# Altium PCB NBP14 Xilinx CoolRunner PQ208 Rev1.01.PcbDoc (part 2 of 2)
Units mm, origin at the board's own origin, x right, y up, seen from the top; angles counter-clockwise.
Board outline 69 x 80.99 mm, 2 copper layers (Top Layer, Bottom Layer); 33 components, 179 nets, 478 pads, 87 vias.
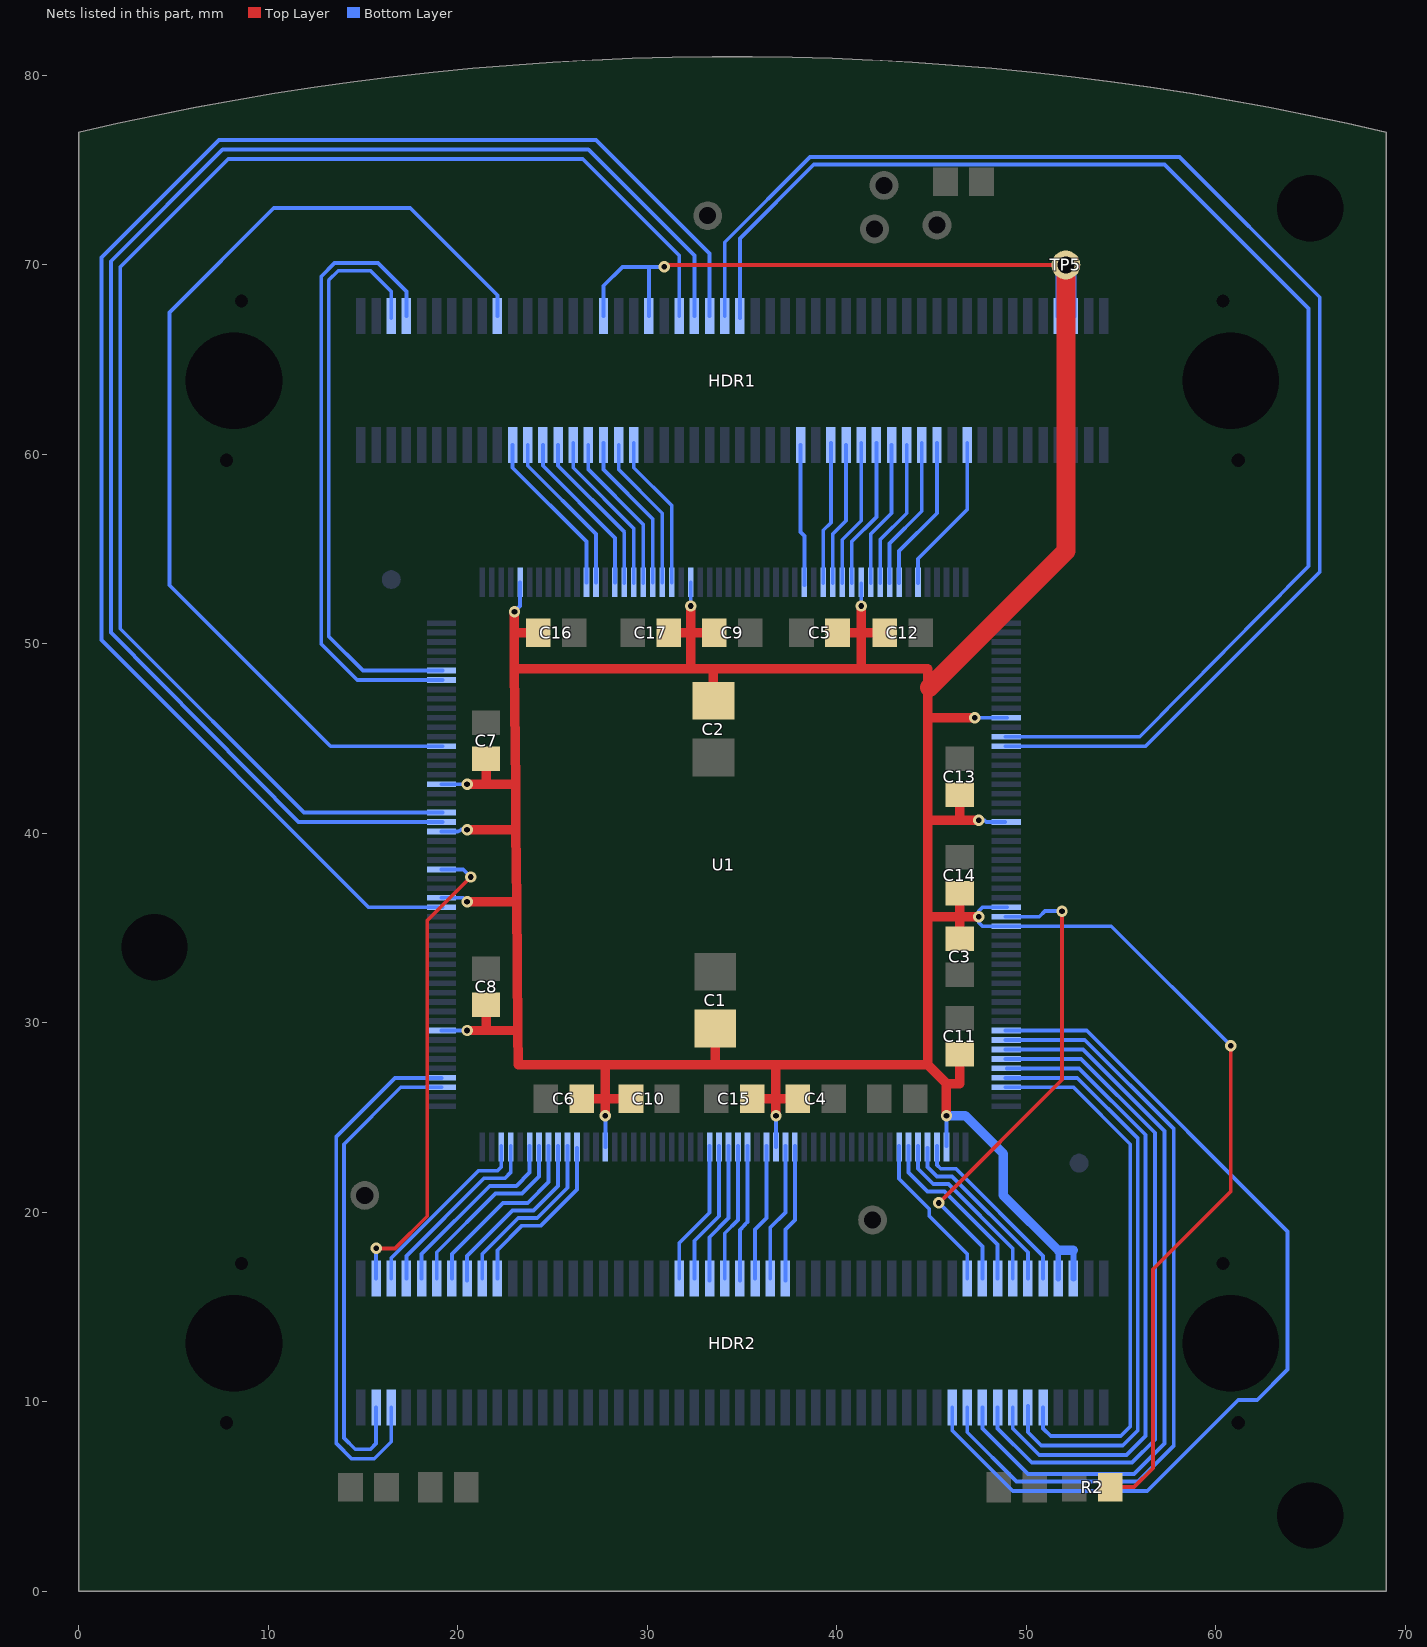
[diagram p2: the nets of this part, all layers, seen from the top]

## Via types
v1: diameter 0.6, hole 0.3, Top Layer to Bottom Layer, tented both sides, 85 vias
v2: diameter 0.9, hole 0.5, Top Layer to Bottom Layer, tented both sides, 2 vias

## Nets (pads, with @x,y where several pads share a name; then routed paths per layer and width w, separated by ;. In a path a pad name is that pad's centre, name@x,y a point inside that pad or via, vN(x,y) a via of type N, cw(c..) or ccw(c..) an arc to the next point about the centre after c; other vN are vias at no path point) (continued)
RAM_ADDR0: HDR1.21 U1.12 | length 8.9
  Bottom Layer w0.2: HDR1.21@22.9,60.5 22.9,59.3 26.8,55.4 U1.12@26.8,53.25
RAM_ADDR1: HDR1.25 U1.15 | length 8.8
  Bottom Layer w0.2: HDR1.25@24.5,60.5 24.5,59.4 28.3,55.6 U1.15@28.3,53.25
RAM_ADDR2: HDR1.29 U1.17 | length 8.7
  Bottom Layer w0.2: HDR1.29@26.1,60.6 HDR1.29@26.1,60.5 26.1,59.3 29.3,56.1 U1.17@29.3,53.2
RAM_ADDR3: HDR1.33 U1.19 | length 8.4
  Bottom Layer w0.2: HDR1.33@27.7,60.6 27.7,59.2 30.3,56.6 U1.19@30.3,53.25
RAM_ADDR4: HDR1.65 U1.38 | length 7.6
  Bottom Layer w0.2: U1.38@39.8,53.2 39.8,55.8 40.5,56.5 HDR1.65@40.5,60.5
RAM_ADDR5: HDR1.69 U1.40 | length 7.9
  Bottom Layer w0.2: U1.40@40.8,53.2 40.8,55.4 42.1,56.7 HDR1.69@42.1,60.6
RAM_ADDR6: HDR1.73 U1.43 | length 7.9
  Bottom Layer w0.2: U1.43@42.3,53.2 42.3,55.5 43.7,56.9 HDR1.73@43.7,60.5
RAM_ADDR7: HDR1.77 U1.45 | length 8.2
  Bottom Layer w0.2: U1.45@43.3,53.2 43.3,54.9 45.3,56.9 HDR1.77@45.3,60.5 HDR1.77@45.3,60.6
RAM_ADDR8: HDR1.75 U1.44 | length 8.1
  Bottom Layer w0.2: U1.44@42.8,53.2 42.8,55.3 44.5,57 HDR1.75@44.5,60.6
RAM_ADDR9: HDR1.71 U1.42 | length 7.8
  Bottom Layer w0.2: U1.42@41.8,53.2 41.8,55.8 42.9,56.9 HDR1.71@42.9,60.5
RAM_ADDR10: HDR1.67 U1.39 | length 7.8
  Bottom Layer w0.2: U1.39@40.3,53.2 40.3,55.5 41.3,56.5 HDR1.67@41.3,60.6
RAM_ADDR11: HDR1.63 U1.37 | length 7.6
  Bottom Layer w0.2: U1.37@39.3,53.2 39.3,56 39.7,56.4 HDR1.63@39.7,60.6
RAM_ADDR12: HDR1.59 U1.35 | length 7.5
  Bottom Layer w0.2: HDR1.59@38.1,60.5 38.1,55.9 38.3,55.7 U1.35@38.3,53.1
RAM_ADDR13: HDR1.35 U1.20 | length 8.2
  Bottom Layer w0.2: HDR1.35@28.5,60.5 28.5,59.2 30.8,56.9 U1.20@30.8,53.25
RAM_ADDR14: HDR1.31 U1.18 | length 8.5
  Bottom Layer w0.2: HDR1.31@26.9,60.5 26.9,59.2 29.8,56.3 U1.18@29.8,53.2
RAM_ADDR15: HDR1.27 U1.16 | length 8.7
  Bottom Layer w0.2: HDR1.27@25.3,60.5 25.3,59.4 28.8,55.9 U1.16@28.8,53.2
RAM_ADDR16: HDR1.23 U1.13 | length 8.7
  Bottom Layer w0.2: HDR1.23@23.7,60.5 23.7,59.4 27.3,55.8 U1.13@27.3,53.25
RAM_CS: HDR1.37 U1.21 | length 8.2
  Bottom Layer w0.2: HDR1.37@29.3,60.6 29.3,59.3 31.3,57.3 U1.21@31.3,53.25
RED0: HDR1.6 U1.203 | length 30.9
  Bottom Layer w0.2: HDR1.6@16.5,67.2 16.5,68.6 15.4,69.7 13.7,69.7 13.2,69.2 13.2,50.4 15,48.6 U1.203@19.2,48.6
RED1: HDR1.8 U1.202 | length 33.3
  Bottom Layer w0.2: HDR1.8@17.3,67.3 17.3,68.6 15.8,70.1 13.5,70.1 12.8,69.4 12.8,50 14.7,48.1 U1.202@19.2,48.1
REF_CLK: HDR2.4 U1.182 | length 25.7
  Top Layer w0.2: v1(15.7,18.1) 16.7,18.1 18.4,19.8 18.4,35.4 v1@20.8,37.8
  Bottom Layer w0.2: HDR2.4@15.7,16.5 v1(15.7,18.1) ; U1.182@19.15,38.1 20.3,38.1 v1(20.7,37.7)
SCL: HDR2.5 U1.160 | length 28.4
  Bottom Layer w0.2: HDR2.5@16.5,9.7 16.5,7.9 15.6,7 14.4,7 13.6,7.8 13.6,24 16.7,27.1 U1.160@19.15,27.1
SDA: HDR2.3 U1.159 | length 25.9
  Bottom Layer w0.2: HDR2.3@15.7,9.7 15.7,7.8 15.4,7.5 14.6,7.5 14,8.1 14,23.6 17,26.6 U1.159@19.15,26.6
SP0: HDR2.79 U1.96 | length 49.5
  Bottom Layer w0.2: HDR2.79@46.1,9.7 46.1,8.5 49.3,5.3 56.4,5.3 61.2,10.1 62.2,10.1 63.8,11.7 63.8,19 53.2,29.6 U1.96@48.9,29.6
SP1: HDR2.81 U1.97 | length 41.6
  Bottom Layer w0.2: HDR2.81@46.9,9.7 46.9,8.4 49.5,5.8 55.9,5.8 57.8,7.7 57.8,24.4 53.1,29.1 U1.97@48.9,29.1
SP2: HDR2.83 U1.98 | length 39
  Bottom Layer w0.2: HDR2.83@47.7,9.7 47.7,8.6 50.1,6.2 55.7,6.2 57.3,7.8 57.3,24.3 53,28.6 U1.98@48.9,28.6
SP3: HDR2.85 U1.99 | length 36.4
  Bottom Layer w0.2: HDR2.85@48.5,9.7 48.5,8.6 50.3,6.8 55.6,6.8 56.8,8 56.8,24.2 52.9,28.1 U1.99@48.9,28.1
SP4: HDR2.87 U1.100 | length 33.7
  Bottom Layer w0.2: U1.100@49,27.6 52.8,27.6 56.3,24.1 56.3,8.2 55.3,7.2 50.7,7.2 49.3,8.6 HDR2.87@49.3,9.7
SP5: HDR2.89 U1.101 | length 31.5
  Bottom Layer w0.2: U1.101@48.9,27.1 52.7,27.1 55.9,23.9 55.9,8.5 55.1,7.7 50.8,7.7 50.1,8.4 HDR2.89@50.1,9.8
SP6: HDR2.91 U1.102 | length 28.8
  Bottom Layer w0.2: U1.102@48.9,26.6 52.5,26.6 55.5,23.6 55.5,8.7 55,8.2 51.3,8.2 50.9,8.6 HDR2.91@50.9,9.7
SP7: HDR2.92 U1.108 | length 9.8
  Bottom Layer w0.2: U1.108@45.3,23.5 45.3,22.5 45.5,22.3 46.3,22.3 50.9,17.7 HDR2.92@50.9,16.5
SP8: HDR2.90 U1.109 | length 9.6
  Bottom Layer w0.2: U1.109@44.8,23.4 44.8,22.4 45.3,21.9 46.1,21.9 50.1,17.9 HDR2.90@50.1,16.5
SP9: HDR2.88 U1.110 | length 9.5
  Bottom Layer w0.2: U1.110@44.3,23.5 44.3,22.3 45.1,21.5 45.9,21.5 49.3,18.1 HDR2.88@49.3,16.5
SP10: HDR2.86 U1.111 | length 9.5
  Bottom Layer w0.2: U1.111@43.8,23.5 43.8,22.1 44.8,21.1 45.7,21.1 48.5,18.3 HDR2.86@48.5,16.5
SP11: HDR2.84 U1.84 | length 26.2
  Top Layer w0.2: v1(45.4,20.5) 51.9,27 v1(51.9,35.9)
  Bottom Layer w0.2: v1(45.4,20.5) 47.7,18.2 HDR2.84@47.7,16.5 ; U1.84@48.9,35.6 50.7,35.6 51,35.9 v1(51.9,35.9)
SP12: HDR2.82 U1.112 | length 8.5
  Bottom Layer w0.2: U1.112@43.3,23.5 43.3,21.774 44.89,20.184 44.89,19.81 46.9,17.8 HDR2.82@46.9,16.5
SPI_CLK: HDR1.46 U1.187 | length 80
  Bottom Layer w0.2: U1.187@19.2,40.6 11.6,40.6 1.7,50.6 1.7,70.2 7.6,76.1 26.9,76.1 32.5,70.5 HDR1.46@32.5,67.3
SPI_DIN: HDR1.44 U1.188 | length 77.3
  Bottom Layer w0.2: U1.188@19.2,41.1 11.9,41.1 2.2,50.8 2.2,69.9 7.9,75.6 26.6,75.6 31.7,70.5 HDR1.44@31.7,67.3
SPI_DOUT: HDR1.50 U1.66 | length 75.1
  Bottom Layer w0.2: HDR1.50@34.1,67.3 34.1,71.2 38.6,75.7 58.1,75.7 65.5,68.3 65.5,53.8 56.3,44.6 U1.66@48.9,44.6
SPI_MODE: HDR1.52 U1.65 | length 72.3
  Bottom Layer w0.2: HDR1.52@34.9,67.2 34.9,71.4 38.8,75.3 57.3,75.3 64.9,67.7 64.9,54.1 56,45.1 U1.65@48.9,45.1
SPI_SEL: HDR1.48 U1.178 | length 84.5
  Bottom Layer w0.2: U1.178@19.2,36.1 15.3,36.1 1.2,50.2 1.2,70.4 7.4,76.6 27.3,76.6 33.3,70.6 HDR1.48@33.3,67.3
SW0: HDR2.44 U1.132 | length 7.7
  Bottom Layer w0.2: HDR2.44@31.7,16.5 31.7,18.385 33.307,19.993 ; 33.3,20 U1.132@33.3,23.5
SW1: HDR2.46 U1.131 | length 7.5
  Bottom Layer w0.2: HDR2.46@32.5,16.5 32.5,18.5 33.8,19.8 U1.131@33.8,23.5
SW2: HDR2.48 U1.130 | length 7.5
  Bottom Layer w0.2: HDR2.48@33.3,16.4 33.3,18.691 34.3,19.7 U1.130@34.3,23.5
SW3: HDR2.50 U1.129 | length 7.3
  Bottom Layer w0.2: HDR2.50@34.1,16.5 34.1,18.9 34.8,19.6 U1.129@34.8,23.5
SW4: HDR2.52 U1.128 | length 7.3
  Bottom Layer w0.2: HDR2.52@34.9,16.4 34.9,19.077 35.3,19.5 U1.128@35.3,23.5
SW5: HDR2.54 U1.126 | length 7.2
  Bottom Layer w0.2: HDR2.54@35.7,16.5 35.7,19.1 36.3,19.7 U1.126@36.3,23.5
SW6: HDR2.56 U1.124 | length 7.3
  Bottom Layer w0.2: HDR2.56@36.5,16.5 36.5,19.2 37.3,20 U1.124@37.3,23.5
SW7: HDR2.58 U1.123 | length 7.3
  Bottom Layer w0.2: HDR2.58@37.3,16.4 37.3,19.1 37.8,19.6 U1.123@37.8,23.5
SWC0: HDR2.18 U1.147 | length 9.4
  Bottom Layer w0.2: HDR2.18@21.3,16.5 21.3,17.8 23.2,19.7 24.2,19.7 25.8,21.3 U1.147@25.8,23.5
SWC1: HDR2.16 U1.148 | length 9.7
  Bottom Layer w0.2: HDR2.16@20.5,16.4 20.5,17.7 22.9,20.1 24,20.1 25.3,21.4 U1.148@25.3,23.5
SWC2: HDR2.14 U1.149 | length 9.9
  Bottom Layer w0.2: HDR2.14@19.7,16.5 19.7,17.8 22.4,20.5 23.7,20.5 24.8,21.6 U1.149@24.8,23.5
SWC3: HDR2.6 U1.154 | length 10
  Bottom Layer w0.2: HDR2.6@16.5,16.5 16.5,17.6 21.1,22.2 22.1,22.2 22.3,22.4 U1.154@22.3,23.5
SWR0: HDR2.20 U1.146 | length 9.2
  Bottom Layer w0.2: HDR2.20@22.1,16.5 22.1,18 23.4,19.3 24.4,19.3 26.3,21.2 U1.146@26.3,23.4
SWR1: HDR2.12 U1.150 | length 10.1
  Bottom Layer w0.2: HDR2.12@18.9,16.5 18.9,17.9 22,21 23.4,21 24.3,21.9 U1.150@24.3,23.5
SWR2: HDR2.10 U1.151 | length 10.2
  Bottom Layer w0.2: HDR2.10@18.1,16.5 18.1,17.8 21.7,21.4 23.1,21.4 23.8,22.1 U1.151@23.8,23.5
SWR3: HDR2.8 U1.153 | length 9.9
  Bottom Layer w0.2: HDR2.8@17.3,16.5 17.3,17.7 21.4,21.8 22.5,21.8 22.8,22.1 U1.153@22.8,23.5
TEST: HDR1.81 U1.47 | length 8.5
  Bottom Layer w0.2: U1.47@44.3,53.2 44.3,54.5 46.9,57.1 HDR1.81@46.9,60.5 HDR1.81@46.9,60.6
VCC: C1.1 C2.1 C3.1 C4.1 C5.1 C6.1 C7.1 C8.1 C9.1 C10.1 C11.1 C12.1 C13.1 C14.1 C15.1 C16.1 C17.1 HDR1.34 HDR1.40 HDR1.94 HDR1.96 HDR2.94 HDR2.96 R2.1 TP5.1 U1.5 U1.23 U1.41 U1.63 U1.74 U1.83 U1.85 U1.107 U1.125 U1.143 U1.165 U1.179 U1.186 U1.191 | length 281.7
  Top Layer w0.2: v1(30.9,69.9) 31,70 31.3,70 TP5.1@52.2,70 ; R2.1@54.4,5.5 55.7,5.5 56.7,6.5 56.7,17 60.8,21.1 v1(60.8,28.8)
  Top Layer w0.5: v1(20.5,29.6) 23.182,29.6 ; v1(20.5,36.4) 23.117,36.4 ; v1(20.5,40.2) 23.081,40.2 ; v1(20.5,42.6) 23.058,42.6 ; 21.5,29.6 C8.1@21.5,30.9 ; 21.5,42.6 C7.1@21.5,44 ; 23,50.6 C16.1@24.3,50.6 ; v1(23,51.7) 23,48.7 ; C6.1@26.5,26 27.8,26 C10.1@29.2,26 ; v1(27.8,25.1) 27.8,27.7 ; C17.1@31.1,50.6 C9.1@33.6,50.6 ; 32.3,48.7 32.3,50.6 v1(32.3,52) ; C2.1@33.5,46.9 33.5,48.7 ; 33.6,27.8 C1.1@33.6,29.7 ; C15.1@35.5,26 C4.1@38,26 ; v1(36.8,25.1) 36.8,27.8 ; C5.1@40.1,50.6 C12.1@42.6,50.6 ; 41.3,48.7 v1(41.3,52) ; 44.8,35.6 v1(47.5,35.6) ; 44.8,40.7 v1(47.5,40.7) ; 44.8,46.1 v1(47.3,46.1) ; v1(45.8,25.1) 45.8,26.8 ; C11.1@46.5,28.3 46.5,26.8 45.8,26.8 ; C3.1@46.5,34.4 C14.1@46.5,36.8 ; 46.5,40.7 C13.1@46.5,42 ; 23,48.7 44.8,48.7 44.8,27.8 ; 23,48.7 23.058,42.6 ; 23.058,42.6 23.081,40.2 ; 23.081,40.2 23.117,36.4 ; 23.117,36.4 23.182,29.6 ; 23.182,29.6 23.2,27.8 44.8,27.8 ; 44.8,27.8 45.8,26.8
  Top Layer w1: 44.9,47.7 52.1,54.9 TP5.1@52.1,70
  Bottom Layer w0.2: U1.165@19.15,29.6 v1(20.5,29.6) ; U1.179@19.15,36.6 20.3,36.6 v1(20.5,36.4) ; U1.186@19.15,40.1 20,40.1 20.2,40.2 v1(20.5,40.2) ; U1.191@19.15,42.6 v1(20.5,42.6) ; v1(23,51.7) 23.3,52 U1.5@23.3,53.25 ; HDR1.34@27.7,67.3 27.7,68.9 28.7,69.9 30.1,69.9 ; U1.143@27.8,23.45 v1(27.8,25.1) ; HDR1.40@30.1,67.3 30.1,67.6 30.1,69.9 ; v1(30.9,69.9) 30.1,69.9 ; v1(32.3,52) U1.23@32.3,53.25 ; U1.125@36.8,23.45 v1(36.8,25.1) ; v1(41.3,52) U1.41@41.3,53.2 ; U1.107@45.8,23.5 v1(45.8,25.1) ; v1(47.3,46.1) U1.63@49,46.1 ; v1(47.5,40.7) 47.8,40.7 47.9,40.6 U1.74@48.9,40.6 ; U1.83@49,36.1 47.7,36.1 47.5,35.9 47.5,35.3 47.7,35.1 54.5,35.1 v1(60.8,28.8)
  Bottom Layer w0.3: HDR2.94@51.7,16.5 51.7,18 ; HDR1.94@51.7,67.3 TP5.1@51.7,70 ; HDR2.96@52.5,16.5 52.5,18 ; HDR1.96@52.5,67.3 TP5.1@52.5,70
  Bottom Layer w0.5: v1(45.8,25.1) 46.8,25.1 48.8,23.1 48.8,20.9 51.7,18 52.5,18
VDRIVE: HDR1.20 U1.195 | length 54.9
  Bottom Layer w0.2: U1.195@19.2,44.6 13.3,44.6 4.8,53.1 4.8,67.5 10.3,73 17.5,73 22.1,68.4 HDR1.20@22.1,67.3
pads on no net: HDR1.91 HDR1.93 HDR1.95 HDR1.97 HDR1.99 HDR1.MH1 HDR1.MH2 HDR1.MH3 HDR1.MH4 HDR1.MH5 HDR1.MH6 HDR2.76 HDR2.78 HDR2.80 HDR2.93 HDR2.95 HDR2.97 HDR2.99 HDR2.MH1 HDR2.MH2 HDR2.MH3 HDR2.MH4 HDR2.MH5 HDR2.MH6 U1.1 U1.2 U1.51 U1.52 U1.53 U1.54 U1.103 U1.104 U1.105 U1.106 U1.155 U1.156 U1.157 U1.158 U1.207 U1.208

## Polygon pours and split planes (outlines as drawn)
VCC on Top Layer "Top Layer-VCC" (solid, remove dead copper, pour order 1001): 21.6,50.3 46.5,50.3 46.5,26.1 21.6,26.1
GND on Top Layer "Top Layer-GND" (solid, remove dead copper, pour order 1000): 0,0 69,0 69,81 0,81
GND on Bottom Layer "Bottom Layer-GND" (solid, remove dead copper, pour order 1002): 0,0 69,0 69,81 0,81

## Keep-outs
Bottom Layer:
  circle w0.2: c16.5,53.4 r2
  circle w0.2: c52.8,22.6 r2
Keep-Out Layer:
  lines w1.8: 68.999,77 ccw(c34.5,-69.801) 0.001,77 0,0 69,0 ; 69.1,0 69.1,77

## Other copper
Bottom Layer:
  rectangle net VCC: 51.6,68.6 52.6,70.6

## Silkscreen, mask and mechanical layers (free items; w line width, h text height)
Top Overlay:
  circle w0.127: c65,73 r2.5
  circle w0.127: c65,4 r2.5
  circle w0.127: c4,34 r2.5
  lines w0.127: 0,1.5 1.5,1.5 1.5,0 ; 0,22.3 1.5,22.3 1.5,23.4 0,23.4 ; 0.001,53.6 1.501,53.6 1.501,54.7 0.001,54.7 ; 0,75.5 1.5,75.5 1.5,77.3 ; 15.7,79.8 15.7,78.1 17,78.1 17,79.9 ; 49.7,80.2 49.7,78.7 51,78.7 51,80.1 ; 67.5,0 67.5,1.5 69,1.5 ; 67.5,77.3 67.5,75.5 69,75.5 ; 68.999,22.3 67.5,22.3 67.5,23.4 69,23.4 ; 69,53.6 67.501,53.6 67.501,54.7 69.001,54.7
  text "PROGRAM" at 16.9,3.1 h0.8
  text "POWER" at 47.6,3.1 h0.8
Bottom Overlay:
  drawing of 852 lines, arcs and shapes, not listed
  text "REV 1.01" at 47.7,76.5 h1.3
  text "NBP14" at 54.9,76.5 h1.3
PCB Boundary:
  the board outline again, w0.25
  text "PCB boundary coincides with centre-line of tracks and arc" at 0,-12 h0.75
Gerber ID:
  text ".Layer_Name" at 0,-6 h0.75
Printout ID:
  text ".Printout_Name" at 0,-10 h0.75
Design Information:
  drawing of 719 lines, arcs and shapes, not listed
  text "NBP14 REV 1.01" at 317.627,202.041 h1.27
  text "DESIGN INFORMATION" at 261.62,201.914 h1.52
  text "BOARD NAME:" at 299.212,201.914 h1.52
  text "BOARD TECHNOLOGY" at 261.62,199.374 h1.52
  text "BOARD SIZE (REFER ALSO PROFILING INFORMATION)" at 309.88,199.374 h1.27
  text "69.00mm" at 312.6,197.1 h1.52
  text "11.811" at 277.419,197.012 h1.52
  text "81.00mm" at 335.6,197 h1.52
  text "7.874" at 291.389,196.885 h1.52
  text "7.874" at 264.446,196.834 h1.52
  text "X" at 328.549,196.326 h1.78
  text "(MIN. TRACK/   PADS  /   CLEARANCE     IN 0.001'')" at 260.096,194.294 h1.27
  text "MINIMUM ANNULAR RING 0.05MM (0.002'') EXTERNAL PER IPC-2221 CLASS 3 LEVEL C AND IS THE" at 261.62,191.754 h1.27
  text "MANUFACTURING REGISTRATION ALLOWANCE" at 261.62,189.468 h1.27
  text "LAND SIZE CALCULATION MINIMUM - NOMINAL HOLE SIZE + 0.508MM (0.020'')" at 261.62,186.674 h1.27
  text "AS INSTRUCTED" at 347.65,182.28 h1.52
  text "X" at 299.263,182.153 h1.52
  text "CIRCUIT TYPE:" at 261.62,182.102 h1.52
  text "SS" at 284.48,182.102 h1.27
  text "DS" at 302.26,182.102 h1.27
  text "X" at 316.865,182.102 h1.52
  text "PTH" at 320.04,182.102 h1.27
  text "ML" at 330.962,182.102 h1.27
  text "No. OFF" at 337.82,182.102 h1.27
  text "FINGER CONNECTOR DIM PER:" at 261.62,179.054 h1.52
  text "AS SHOWN" at 337.82,179.054 h1.27
  text "No. OFF TOTAL" at 278.384,176.26 h1.52
  text "ONE SIDE" at 320.04,176.26 h1.27
  text "BOTH SIDES" at 337.82,176.006 h1.27
  text "VIAS:" at 261.62,173.339 h1.52
  text "NONE" at 273.05,173.339 h1.14
  text "X" at 281.432,173.339 h1.52
  text "FEED THRU'" at 284.48,173.339 h1.14
  text "X" at 299.212,173.339 h1.52
  text "TENTED" at 302.26,173.339 h1.14
  text "BURIED LAYER SEQUENCE" at 320.04,173.339 h1.14
  text "UNIQUE DRILL" at 284.48,170.291 h1.14
  text "2 SIZE" at 302.26,170.291 h1.14
  text "BLIND LAYER SEQUENCE" at 320.04,170.291 h1.14
  text "Layer Stack Manager (Protel)" at 297.053,168.005 h1.27
  text "X" at 334.772,168.005 h1.52
  text "AS SHOWN" at 337.82,168.005 h1.27
  text "LAYER CONSTRUCTION PER:" at 261.62,167.878 h1.52
  text "Protel" at 342.646,165.338 h1.27
  text "(PFW)" at 352.933,165.211 h1.27
  text "ARTWORK:" at 261.62,165.084 h1.52
  text "MANUAL" at 284.48,165.084 h1.27
  text "DIGITISED" at 302.26,165.084 h1.27
  text "X" at 316.992,165.084 h1.52
  text "CAD" at 320.04,165.084 h1.27
  text "TYPE" at 330.962,165.084 h1.27
  text "ARTWORK/PATTERN MASTER LIST" at 261.62,160.385 h1.52
  text "DESCRIPTION" at 262.89,157.972 h1.27
  text "DRAWING No./CAD FILE REF." at 281.559,157.972 h1.27
  text "LAYER NAME" at 322.834,157.972 h1.27
  text "GERBER FILE REF" at 343.586,157.896 h1.27
  text "PCB FILE" at 261.366,155.432 h1.27
  text "BOCD_CoolRunner_XPLA3_PQ208" at 281.237,155.356 h1.14
  text "PcbDoc" at 312.979,155.356 h1.02
  text "Top Paste Mask" at 321.158,152.892 h1.02
  text "GTP" at 363.779,152.816 h1.27
  text "GERBER FILE" at 261.366,152.765 h1.27
  text "GTO" at 363.728,150.327 h1.27
  text "Top Overlay" at 321.158,150.301 h1.02
  text "GERBER FILE" at 261.366,150.225 h1.27
  text "Top Solder Mask" at 321.158,147.863 h1.02
  text "GTS" at 363.779,147.736 h1.27
  text "GERBER FILE" at 261.366,147.685 h1.27
  text "TOP LAYER" at 321.158,145.272 h1.02
  text "GTL" at 363.779,145.196 h1.27
  text "GERBER FILE" at 261.366,145.145 h1.27
  text "BOTTOMLAYER" at 321.158,142.732 h1.02
  text "GBL" at 363.779,142.656 h1.27
  text "GERBER FILE" at 261.366,142.605 h1.27
  text "Bottom Solder Mask" at 321.158,140.243 h1.02
  text "GBS" at 363.779,140.116 h1.27
  text "GERBER FILE" at 261.366,140.065 h1.27
  text "Bottom Overlay" at 321.158,137.652 h1.02
  text "GBO" at 363.779,137.576 h1.27
  text "GERBER FILE" at 261.366,137.525 h1.27
  text "Bottom Paste Mask" at 321.158,135.163 h1.02
  text "GBP" at 363.779,135.036 h1.27
  text "GERBER FILE" at 261.366,134.985 h1.27
  text "PCB Boundary" at 321.158,132.572 h1.02
  text "GM1" at 363.779,132.496 h1.27
  text "GERBER FILE" at 261.366,132.445 h1.27
  text "APERTURE LIST" at 261.366,130.032 h1.27
  text "APR" at 313.979,129.956 h1.27
  text "DRILL REPORT" at 261.366,127.492 h1.27
  text "DRR" at 313.979,127.416 h1.27
  text "EXCELLON DRILL" at 261.366,124.952 h1.27
  text "TXT" at 313.979,124.876 h1.27
  text "MATERIAL:" at 261.62,99.298 h1.52
  text "GLASS FIBRE EPOXY RESIN NEMA GRADE FR4 (MIL-S-13949H)" at 287.274,99.044 h1.27
  text "X" at 284.607,98.917 h1.52
  text "THICKNESS:" at 269.494,96.123 h1.27
  text "0.8mm" at 287.274,96.123 h1.27
  text "1.2mm" at 304.927,96.123 h1.27
  text "1.6mm" at 322.58,96.123 h1.27
  text "2.4mm" at 340.36,96.123 h1.27
  text "3.2mm" at 358.14,96.123 h1.27
  text "X" at 320.167,95.996 h1.52
  text "TOLERANCE:" at 269.367,93.075 h1.27
  text "IN A/W IPC-D-300G CLASS" at 287.02,93.075 h1.27
  text "3 LEVEL B" at 321.945,93.075 h1.27
  text "OTHER +/-" at 340.36,93.075 h1.27
  text "X" at 284.607,92.948 h1.52
  text "BOW & TWIST:" at 266.954,90.027 h1.27
  text "IN A/W IPC-D-300G CLASS" at 287.02,90.027 h1.27
  text "3 LEVEL B" at 321.945,90.027 h1.27
  text "AS SHOWN" at 340.487,89.9 h1.27
  text "X" at 284.607,89.773 h1.52
  text "COPPER THICKNESS (FINISHED)" at 269.367,86.725 h1.27
  text "OUTER:" at 274.193,84.439 h1.27
  text "18um" at 287.274,84.439 h1.27
  text "35um" at 314.325,84.439 h1.27
  text "70um" at 340.614,84.439 h1.27
  text "X" at 311.582,84.236 h1.52
  text "INNER SIGNAL:" at 265.811,81.391 h1.27
  text "18um" at 287.274,81.391 h1.27
  text "35um" at 314.325,81.391 h1.27
  text "70um" at 340.614,81.391 h1.27
  text "INNER PWR:" at 269.494,78.343 h1.27
  text "18um" at 287.274,78.343 h1.27
  text "35um" at 314.325,78.343 h1.27
  text "70um" at 340.614,78.343 h1.27
  text "STRUCTURE:" at 261.62,75.295 h1.52
  text "REFER" at 287.274,75.295 h1.27
  text "AS PER DRAWING No." at 287.147,72.12 h1.27
  text "AS SHOWN" at 340.487,72.12 h1.27
  text "X" at 337.947,71.993 h1.52
  text "DRILLING:" at 261.62,69.326 h1.52
  text "VIEWED FROM:" at 266.573,67.04 h1.27
  text "COMPONENT SIDE" at 287.274,67.04 h1.14
  text "SOLDER SIDE" at 314.071,67.04 h1.14
  text "X" at 284.607,66.786 h1.52
  text "REFERENCE:" at 268.859,63.992 h1.27
  text "AS SHOWN" at 287.147,63.865 h1.14
  text "PATTERN MASTER LIST" at 314.198,63.865 h1.14
  text "X" at 337.947,63.865 h1.52
  text "NC_DRILL FILES" at 340.487,63.865 h1.14
  text "X" at 284.607,63.738 h1.52
  text "PTH MINIMUM COPPER THICKNESS:" at 274.701,60.944 h1.27
  text "20um" at 314.325,60.944 h1.27
  text "X" at 311.658,60.817 h1.52
  text "OTHER" at 340.487,60.817 h1.27
  text "NPTH:" at 275.209,57.896 h1.27
  text "TENTED" at 287.147,57.769 h1.14
  text "X" at 311.658,57.769 h1.52
  text "PADS REMOVED" at 314.198,57.769 h1.14
  text "REMOVE PADS" at 340.487,57.769 h1.14
  text "X" at 284.607,57.642 h1.52
  text "2nd DRILL" at 287.147,54.721 h1.14
  text "BOTH" at 314.198,54.721 h1.14
  text "AS SHOWN" at 326.517,54.721 h1.14
  text "NONE" at 340.487,54.721 h1.14
  text "BOARD FINISH:" at 261.62,51.8 h1.52
  text "X" at 284.607,51.673 h1.52
  text "ETCHING" at 287.147,51.673 h1.14
  text "REFER PATTERN MASTER LIST" at 314.198,51.673 h1.14
  text "LEGEND / SCREEN PRINT:" at 281.94,48.752 h1.27
  text "NONE" at 314.198,48.625 h1.14
  text "COMPONENT" at 326.517,48.625 h1.14
  text "SOLDER" at 340.487,48.625 h1.14
  text "X" at 323.977,48.498 h1.52
  text "X" at 337.947,48.498 h1.52
  text "COLOUR:" at 272.161,45.704 h1.27
  text "WHITE" at 287.147,45.577 h1.14
  text "YELLOW" at 314.198,45.577 h1.14
  text "OTHER" at 340.487,45.577 h1.14
  text "X" at 284.607,45.45 h1.52
  text "X" at 284.607,42.529 h1.52
  text "LIQUID PHOTOIMAGEABLE" at 287.147,42.529 h1.14
  text "SCREEN PRINT" at 326.517,42.529 h1.14
  text "MATTE" at 287.147,39.481 h1.14
  text "GLOSS" at 299.847,39.481 h1.14
  text "GREEN" at 314.198,39.481 h1.14
  text "BLUE" at 326.517,39.481 h1.14
  text "G/Y" at 340.487,39.481 h1.14
  text "OTHER" at 351.917,39.481 h1.14
  text "X" at 297.18,39.354 h1.52
  text "SOLDER MASK COLOUR:" at 261.62,36.56 h1.14
  text "BLACK" at 287.147,36.433 h1.14
  text "GREEN" at 299.847,36.433 h1.14
  text "YELLOW" at 314.198,36.433 h1.14
  text "BLUE" at 326.517,36.433 h1.14
  text "OTHER" at 340.487,36.433 h1.14
  text "X" at 284.48,36.306 h1.52
  text "TRACK FINISH:" at 261.62,33.512 h1.52
  text "SELECTIVE SOLDER (HASL)" at 287.147,33.385 h1.14
  text "REFLOW SOLDER" at 326.517,33.385 h1.14
  text "SELECTIVE GOLD" at 287.147,30.337 h1.14
  text "um  (AREA" at 314.198,30.337 h1.14
  text "sq. mm)" at 342.011,30.337 h1.14
  text "X" at 284.607,27.289 h1.52
  text "IMMERSION GOLD" at 287.147,27.289 h1.14
  text "OTHER" at 326.517,27.289 h1.14
  text "EDGE BOARD" at 261.62,24.368 h1.52
  text "1.3um HARD GOLD OVER 5um     NICKEL / TIN-NICKEL" at 287.147,24.241 h1.14
  text "CONTACTS:" at 261.62,22.209 h1.52
  text "HARD FINISH GOLDE PLATE" at 287.147,21.193 h1.14
  text "OTHER" at 326.517,21.193 h1.14
  text "AS SHOWN" at 287.147,18.145 h1.14
  text "REFER" at 326.517,18.145 h1.14
  text "PROFILING:" at 261.62,15.097 h1.52
  text "AS DIMENSIONED, MEASURED AND CUT FROM SPECIFIED DATUM." at 287.147,15.097 h1.14
  text "X" at 284.607,14.97 h1.52
  text "REFER PCB BLANK DWG No." at 287.274,12.176 h1.27
  text "USE PROFILE / ROUTE TAPE SUPPLIED (REFER PATTERN MASTER LIST)" at 287.274,9.128 h1.27
  text "SQUARE CUT" at 287.274,6.08 h1.27
  text "N.C. ROUTE" at 305.054,6.08 h1.27
  text "V. SCORE" at 322.834,6.08 h1.27
  text "BLANK" at 340.614,6.08 h1.27
  text "ACCEPTABILITY:" at 261.62,3.413 h1.52
  text "MATERIALS AND WORKMANSHIP FOR ALL PRINTED WIRING BOARDS TO MEET" at 283.845,3.286 h1.27
  text "OR EXCEED THE REQUIREMENTS OF:" at 283.845,0.492 h1.27
  text "IPC-6011/12 AND IPC-A-600E" at 287.401,-2.175 h1.27
  text "1" at 322.961,-2.175 h1.27
  text "2" at 331.851,-2.175 h1.27
  text "X" at 329.184,-2.302 h1.52
  text "X" at 284.734,-2.429 h1.52
  text "3" at 340.741,-4.334 h1.27
  text "UL CERTIFICATION" at 287.401,-5.223 h1.27
  text "AUSTEL" at 322.961,-5.223 h1.27
  text "X" at 284.734,-5.35 h1.52
  text "ML-P-55110F GRP" at 286.893,-8.271 h1.02
  text "A" at 305.181,-8.271 h1.27
  text "B" at 314.071,-8.271 h1.27
  text "AS2546" at 322.961,-8.271 h1.27
  text "OTHER" at 340.741,-8.271 h1.27
  text "ADDITIONAL" at 261.62,-11.192 h1.52
  text "NONE" at 287.401,-11.446 h1.27
  text "SAMPLE PLAN" at 305.181,-11.446 h1.27
  text "MIL-P-55110E SERIAL Nos. PER ORDER" at 322.961,-11.446 h1.27
  text "REQUIREMENTS:" at 261.62,-13.605 h1.52
  text "NONE" at 287.401,-14.494 h1.27
  text "ML-P-55110F GRP" at 304.673,-14.494 h1.02
  text "A" at 322.961,-14.494 h1.27
  text "B" at 331.851,-14.494 h1.27
  text "IPC CLASS:" at 337.82,-14.494 h1.27
  text "1" at 353.314,-14.494 h1.27
  text "2" at 359.664,-14.494 h1.27
  text "3" at 366.014,-14.494 h1.27
  text "QUALITY RELEASE REPORT" at 305.181,-17.542 h1.27
  text "OTHER" at 345.694,-17.542 h1.27
  text "PER ORDER" at 354.203,-17.669 h1.27
  text "X" at 343.027,-17.796 h1.52
  text "NONE" at 305.181,-20.59 h1.27
  text "REQUIRED" at 322.961,-20.59 h1.27
  text "PER ORDER" at 345.821,-20.59 h1.27
  text "ELECTRICAL TEST:" at 261.62,-20.717 h1.52
  text "X" at 320.294,-20.717 h1.52
  text "NONE" at 305.181,-23.638 h1.27
  text "1 SIDE" at 322.834,-23.638 h1.14
  text "2 SIDES" at 334.01,-23.638 h1.14
  text "MIN. PITCH" at 345.694,-23.638 h1.27
  text "0.65mm" at 359.283,-23.638 h1.27
  text "SURFACE MOUNT:" at 261.62,-23.765 h1.52
  text "X" at 331.775,-23.841 h1.52
  text "NONE" at 305.181,-26.686 h1.27
  text "FOIL" at 322.961,-26.686 h1.27
  text "LEGEND" at 334.391,-26.686 h1.27
  text "REFER" at 345.694,-26.686 h1.27
  text "MANUFACTURER'S ID/LOGO:" at 261.62,-26.813 h1.52
  text "ISO9001/AS3901" at 308.991,-29.734 h1.27
  text "NONE" at 345.694,-29.734 h1.27
  text "MANUFACTURER'S ACCREDITATION:" at 261.62,-29.861 h1.52
  text "X" at 306.324,-29.861 h1.52
  text "PER ORDER" at 305.181,-32.782 h1.27
  text "REFER" at 322.961,-32.782 h1.27
  text "PACKAGING AND HANDLING:" at 261.62,-32.909 h1.52
  text "X" at 302.514,-33.036 h1.52
Sheet:
  drawing of 1882 lines, arcs and shapes, not listed
  text "1" at 3.717,207.391 h1.78
  text "2" at 52.756,207.391 h1.78
  text "3" at 102.015,207.391 h1.78
  text "4" at 151.308,207.391 h1.78
  text "5" at 200.584,207.391 h1.78
  text "6" at 249.606,207.391 h1.78
  text "7" at 299.136,207.391 h1.78
  text "8" at 348.158,207.391 h1.78
  text "A" at -18.415,173.406 h1.78
  text "A" at 370.205,173.406 h1.78
  text "B" at -18.415,102.794 h1.78
  text "B" at 370.205,102.794 h1.78
  text "C" at -18.415,32.182 h1.78
  text "C" at 370.205,32.182 h1.78
  text "D" at -18.415,-37.922 h1.78
  text "D" at 370.205,-37.922 h1.78
  text "ENGINEER:" at 255.27,-38.1 h1.14
  text "TITLE:" at 293.37,-38.1 h1.14
  text "PCB DESIGNER:" at 255.27,-45.593 h1.14
  text "DATE:" at 255.27,-53.34 h1.14
  text "PART NO.:" at 293.37,-53.34 h1.14
  text "REV:" at 346.71,-53.34 h1.14
  text "Altium Limited" at 222.25,-55.88 h1.78
  text ".PRINT_DATE" at 256.54,-56.388 h1.78
  text "12a Rodborough Rd" at 222.25,-58.42 h1.78
  text "Frenchs Forest" at 222.25,-60.96 h1.78
  text "FILE NAME:" at 255.27,-60.96 h1.14
  text "DWG NO:" at 293.37,-60.96 h1.14
  text "SCALE:" at 346.71,-60.96 h1.14
  text "NSW 2086" at 222.25,-63.5 h1.78
  text ".PCB_FILE_NAME_NO_PATH" at 256.54,-64.008 h1.78
  text "1" at 3.717,-69.469 h1.78
  text "2" at 52.756,-69.469 h1.78
  text "3" at 102.015,-69.469 h1.78
  text "4" at 151.308,-69.469 h1.78
  text "5" at 200.584,-69.469 h1.78
  text "6" at 249.606,-69.469 h1.78
  text "7" at 299.136,-69.469 h1.78
  text "8" at 348.158,-69.469 h1.78
Drill Drawing:
  text ".Legend" at 0,-8 h0.75

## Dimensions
34.5,-69.801 to 34.5,84 on Dimensions
0,0 to 0.001,77 on Dimensions
0,0 to 69,0 on Dimensions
